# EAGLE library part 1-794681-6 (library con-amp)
Micro MATE-N-LOK Connectors grid 1.5mm Dual Row Through Hole Vertical Metal Through Hole Holddowns Source: ENG_CD_794681_E.pdf
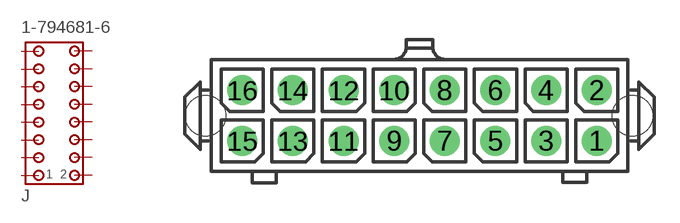
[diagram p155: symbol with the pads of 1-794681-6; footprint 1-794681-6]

Designator prefix J

## 1-794681-6 (MF: TYCO ELECTRONICS; MPN: 1-794681-6; OC_FARNELL: unknown; OC_NEWARK: 10H3812)  [1-794681-6]
1  1  pas
2  2  pas
3  3  pas
4  4  pas
5  5  pas
6  6  pas
7  7  pas
8  8  pas
9  9  pas
10  10  pas
11  11  pas
12  12  pas
13  13  pas
14  14  pas
15  15  pas
16  16  pas

## Footprint 1-794681-6 (pad centres in mm)
Micro MATE-N-LOK Connectors grid 1.5mm Dual Row Through Hole Vertical Metal Through Hole Holddowns Source: ENG_CD_794681_E.pdf
drill 1 pad 1.778 round: 1 10.5,-1.5; 2 10.5,1.5; 3 7.5,-1.5; 4 7.5,1.5; 5 4.5,-1.5; 6 4.5,1.5; 7 1.5,-1.5; 8 1.5,1.5; 9 -1.5,-1.5; 10 -1.5,1.5; 11 -4.5,-1.5; 12 -4.5,1.5; 13 -7.5,-1.5; 14 -7.5,1.5; 15 -10.5,-1.5; 16 -10.5,1.5
hole 2.4 at 12.63,0
hole 2.4 at -12.67,0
